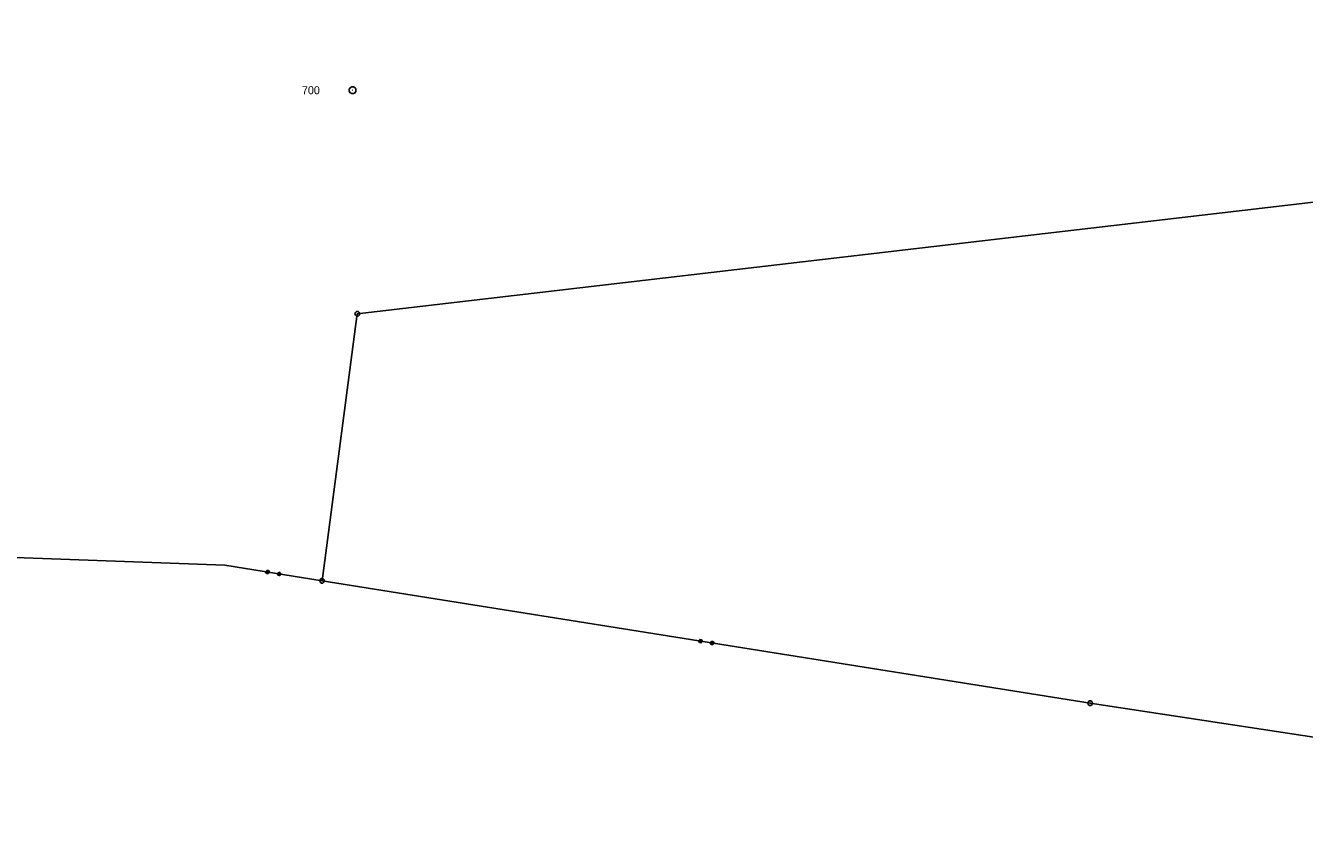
# Model space of a CAD drawing. Extents: x -871430 to -870620, y -1010094 to -1009649.
# Drawn here: x -871226 to -871158.1, y -1010051.2 to -1010009 of the extents above; entities that cross this region are included whole.
import ezdxf

# ---------------------------------------------------------------- set-up
doc = ezdxf.new("R2010")
doc.units = 0
doc.layers.add('Vrstva 1', color=7, linetype='Continuous')
doc.layers.add('Vrstva 8', color=7, linetype='Continuous')

msp = doc.modelspace()

# ---------------------------------------------------------------- linework, layer by layer
at = {"layer": 'Vrstva 1'}
for p, q in [((-871077.55, -1010009.01), (-871208.37, -1010024.31)), ((-871208.37, -1010024.31), (-871210.24, -1010038.47)), ((-871215.4, -1010037.65), (-871259.43, -1010036)), ((-871210.24, -1010038.47), (-871215.4, -1010037.65)), ((-871210.24, -1010038.47), (-871169.46, -1010044.97)), ((-871169.46, -1010044.97), (-871128.29, -1010051.24))]:
    msp.add_line(p, q, dxfattribs=at)
for points in [[(-871213.186, -1010038.083), (-871213.225, -1010038.029), (-871213.214, -1010037.962), (-871213.16, -1010037.922), (-871213.093, -1010037.933), (-871213.054, -1010037.987), (-871213.065, -1010038.054), (-871213.119, -1010038.093), (-871213.186, -1010038.083), (-871213.177, -1010038.074), (-871213.117, -1010038.084), (-871213.095, -1010038.067), (-871213.193, -1010038.051), (-871213.21, -1010038.028), (-871213.072, -1010038.05), (-871213.068, -1010038.031), (-871213.207, -1010038.009), (-871213.204, -1010037.989), (-871213.065, -1010038.011), (-871213.062, -1010037.991), (-871213.2, -1010037.969), (-871213.178, -1010037.953), (-871213.079, -1010037.968), (-871213.095, -1010037.945), (-871213.155, -1010037.936)], [(-871212.568, -1010038.181), (-871212.608, -1010038.127), (-871212.597, -1010038.06), (-871212.543, -1010038.021), (-871212.476, -1010038.031), (-871212.437, -1010038.085), (-871212.447, -1010038.152), (-871212.502, -1010038.192), (-871212.568, -1010038.181), (-871212.564, -1010038.172), (-871212.505, -1010038.181), (-871212.482, -1010038.164), (-871212.581, -1010038.149), (-871212.598, -1010038.126), (-871212.459, -1010038.148), (-871212.456, -1010038.128), (-871212.594, -1010038.106), (-871212.591, -1010038.086), (-871212.453, -1010038.108), (-871212.45, -1010038.088), (-871212.588, -1010038.066), (-871212.565, -1010038.05), (-871212.466, -1010038.066), (-871212.483, -1010038.043), (-871212.542, -1010038.033)], [(-871190.102, -1010041.599), (-871190.062, -1010041.653), (-871190.073, -1010041.72), (-871190.127, -1010041.759), (-871190.194, -1010041.749), (-871190.233, -1010041.694), (-871190.223, -1010041.628), (-871190.168, -1010041.588), (-871190.102, -1010041.599), (-871190.106, -1010041.608), (-871190.165, -1010041.599), (-871190.188, -1010041.615), (-871190.089, -1010041.631), (-871190.072, -1010041.654), (-871190.211, -1010041.632), (-871190.214, -1010041.652), (-871190.076, -1010041.674), (-871190.079, -1010041.694), (-871190.217, -1010041.672), (-871190.22, -1010041.691), (-871190.082, -1010041.713), (-871190.105, -1010041.73), (-871190.204, -1010041.714), (-871190.187, -1010041.737), (-871190.128, -1010041.747)], [(-871189.484, -1010041.697), (-871189.445, -1010041.752), (-871189.456, -1010041.818), (-871189.51, -1010041.858), (-871189.577, -1010041.847), (-871189.616, -1010041.793), (-871189.605, -1010041.726), (-871189.551, -1010041.687), (-871189.484, -1010041.697), (-871189.493, -1010041.706), (-871189.553, -1010041.697), (-871189.575, -1010041.713), (-871189.477, -1010041.729), (-871189.46, -1010041.752), (-871189.598, -1010041.73), (-871189.602, -1010041.75), (-871189.463, -1010041.772), (-871189.466, -1010041.791), (-871189.605, -1010041.769), (-871189.608, -1010041.789), (-871189.47, -1010041.811), (-871189.492, -1010041.828), (-871189.591, -1010041.812), (-871189.575, -1010041.835), (-871189.515, -1010041.844)]]:
    msp.add_lwpolyline(points, dxfattribs=at)
at = {"layer": 'Vrstva 8'}
for p, q in [((-871208.632, -1010012.44), (-871208.608, -1010012.44)), ((-871208.382, -1010024.31), (-871208.358, -1010024.31)), ((-871210.252, -1010038.47), (-871210.228, -1010038.47)), ((-871169.472, -1010044.97), (-871169.448, -1010044.97))]:
    msp.add_line(p, q, dxfattribs=at)
for points in [[(-871208.572, -1010012.26), (-871208.488, -1010012.308), (-871208.44, -1010012.392), (-871208.44, -1010012.49), (-871208.488, -1010012.575), (-871208.572, -1010012.622), (-871208.67, -1010012.622), (-871208.755, -1010012.575), (-871208.802, -1010012.49), (-871208.802, -1010012.392), (-871208.755, -1010012.308), (-871208.67, -1010012.26), (-871208.572, -1010012.26)], [(-871208.332, -1010024.19), (-871208.27, -1010024.238), (-871208.245, -1010024.31), (-871208.27, -1010024.383), (-871208.332, -1010024.43), (-871208.408, -1010024.43), (-871208.47, -1010024.383), (-871208.495, -1010024.31), (-871208.47, -1010024.238), (-871208.408, -1010024.19), (-871208.332, -1010024.19)], [(-871210.202, -1010038.35), (-871210.14, -1010038.398), (-871210.115, -1010038.47), (-871210.14, -1010038.542), (-871210.202, -1010038.59), (-871210.278, -1010038.59), (-871210.34, -1010038.542), (-871210.365, -1010038.47), (-871210.34, -1010038.398), (-871210.278, -1010038.35), (-871210.202, -1010038.35)], [(-871169.422, -1010044.85), (-871169.36, -1010044.898), (-871169.335, -1010044.97), (-871169.36, -1010045.042), (-871169.422, -1010045.09), (-871169.497, -1010045.09), (-871169.56, -1010045.042), (-871169.585, -1010044.97), (-871169.56, -1010044.898), (-871169.497, -1010044.85), (-871169.422, -1010044.85)]]:
    msp.add_lwpolyline(points, dxfattribs=at)

# ---------------------------------------------------------------- texts
msp.add_text('700', height=0.425, dxfattribs=at).set_placement((-871211.31, -1010012.652))

doc.saveas('drawing.dxf')
